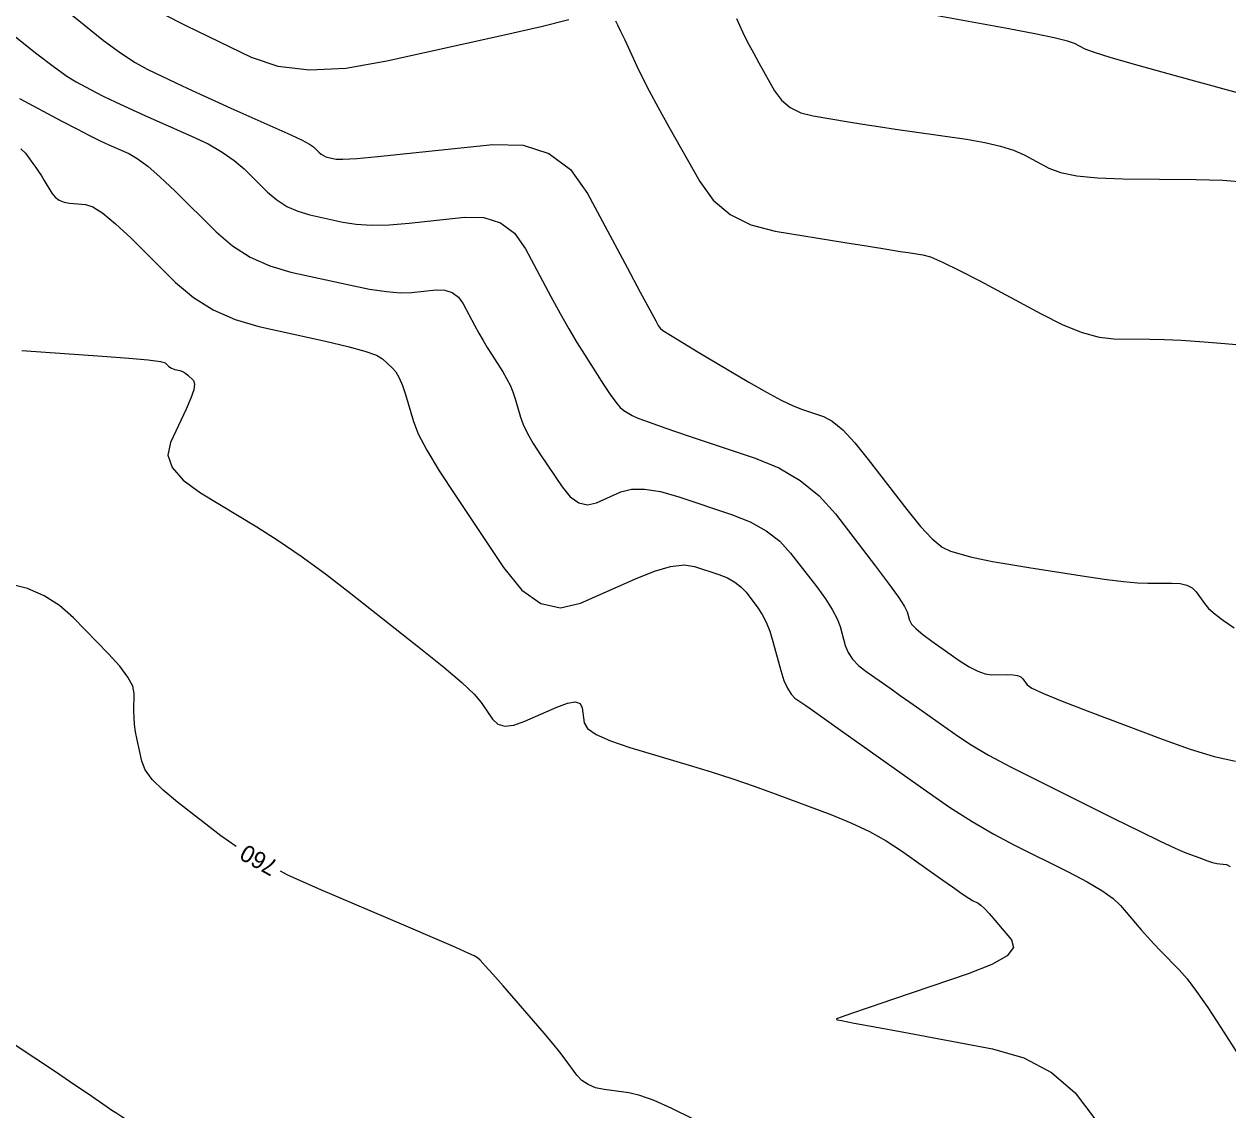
# Model space of a CAD drawing. Extents: x 2082232 to 2083549, y 592624 to 593832.
# Drawn here: x 2082625.36 to 2082675.09, y 592671.24 to 592716.1 of the extents above; entities that cross this region are included whole.
import ezdxf

# ---------------------------------------------------------------- set-up
doc = ezdxf.new("R2010")
doc.units = 0
doc.layers.add('DT_X_Contour_Major', color=7, linetype='Continuous')
doc.layers.add('DT_X_Contour_Minor', color=7, linetype='Continuous')

msp = doc.modelspace()

# ---------------------------------------------------------------- linework, layer by layer
at = {"layer": 'DT_X_Contour_Major'}
for points in [[(2082625.558, 592717.923), (2082627.838, 592716.065), (2082628.641, 592715.429), (2082629.342, 592714.914), (2082629.94, 592714.519), (2082630.435, 592714.245), (2082631.619, 592713.677), (2082632.095, 592713.451), (2082632.634, 592713.202), (2082633.235, 592712.929), (2082633.899, 592712.632), (2082635.755, 592711.808), (2082636.374, 592711.527), (2082636.84, 592711.303), (2082637.153, 592711.136), (2082637.313, 592711.025), (2082637.535, 592710.806), (2082637.622, 592710.731), (2082637.718, 592710.67), (2082637.823, 592710.622), (2082637.936, 592710.59), (2082638.25, 592710.52), (2082638.52, 592710.515), (2082639.095, 592710.552), (2082639.974, 592710.63), (2082641.159, 592710.75), (2082644.725, 592711.126), (2082645.971, 592711.106), (2082647.038, 592710.762), (2082647.924, 592710.096), (2082648.629, 592709.108), (2082650.27, 592706.041), (2082650.812, 592705.029), (2082651.207, 592704.294), (2082651.455, 592703.836), (2082651.556, 592703.655), (2082651.629, 592703.541), (2082651.749, 592703.446), (2082652.057, 592703.247), (2082652.552, 592702.944), (2082653.234, 592702.537), (2082655.302, 592701.314), (2082656.022, 592700.899), (2082656.63, 592700.571), (2082657.125, 592700.331), (2082657.509, 592700.178), (2082658.383, 592699.886), (2082658.744, 592699.694), (2082659.173, 592699.334), (2082659.669, 592698.807), (2082660.231, 592698.114), (2082661.822, 592696.041), (2082662.382, 592695.351), (2082662.871, 592694.834), (2082663.288, 592694.49), (2082663.633, 592694.32), (2082664.456, 592694.098), (2082664.838, 592694.008), (2082665.367, 592693.903), (2082666.042, 592693.784), (2082666.864, 592693.651), (2082669.251, 592693.276), (2082670.08, 592693.153), (2082670.779, 592693.066), (2082671.347, 592693.015), (2082671.783, 592693), (2082672.773, 592693.009), (2082673.113, 592692.989), (2082673.394, 592692.922), (2082673.613, 592692.809), (2082673.773, 592692.649), (2082674.116, 592692.162), (2082674.29, 592691.962), (2082674.554, 592691.728), (2082674.907, 592691.46), (2082675.349, 592691.159)], [(2082634.11, 592682.122), (2082633.477, 592682.564), (2082631.692, 592683.95), (2082631.098, 592684.446), (2082630.653, 592684.895), (2082630.358, 592685.297), (2082630.213, 592685.651), (2082630.026, 592686.532), (2082629.965, 592686.855), (2082629.923, 592687.162), (2082629.9, 592687.453), (2082629.895, 592687.728), (2082629.908, 592688.442), (2082629.845, 592688.745), (2082629.645, 592689.121), (2082629.309, 592689.57), (2082628.837, 592690.09), (2082627.397, 592691.575), (2082626.825, 592692.08), (2082626.189, 592692.482), (2082625.49, 592692.782), (2082624.726, 592692.978)], [(2082652.986, 592670.874), (2082652.115, 592671.303), (2082651.384, 592671.625), (2082650.793, 592671.839), (2082650.341, 592671.945), (2082649.323, 592672.083), (2082648.966, 592672.159), (2082648.659, 592672.285), (2082648.402, 592672.458), (2082648.196, 592672.681), (2082647.711, 592673.34), (2082647.493, 592673.624), (2082647.203, 592673.982), (2082646.84, 592674.414), (2082646.404, 592674.919), (2082645.145, 592676.367), (2082644.725, 592676.846), (2082644.41, 592677.198), (2082644.199, 592677.422), (2082644.093, 592677.519), (2082643.948, 592677.608), (2082643.732, 592677.709), (2082643.19, 592677.947), (2082642.324, 592678.32), (2082641.133, 592678.83), (2082637.523, 592680.37), (2082636.255, 592680.94), (2082635.942, 592681.099)], [(2082624.95, 592673.957), (2082626.648, 592672.822), (2082627.229, 592672.433), (2082627.697, 592672.119), (2082628.052, 592671.878), (2082628.294, 592671.712), (2082628.79, 592671.366), (2082628.981, 592671.236), (2082629.182, 592671.102), (2082629.392, 592670.966), (2082629.612, 592670.827), (2082630.211, 592670.453), (2082630.552, 592670.302), (2082631.128, 592670.128), (2082631.937, 592669.932), (2082632.98, 592669.713), (2082635.484, 592669.217)]]:
    msp.add_lwpolyline(points, dxfattribs=at)
at = {"layer": 'DT_X_Contour_Minor'}
for points in [[(2082631.063, 592716.546), (2082632.063, 592716.024), (2082634.742, 592714.738), (2082635.845, 592714.366), (2082637.146, 592714.216), (2082638.646, 592714.286), (2082640.343, 592714.577), (2082645.132, 592715.647), (2082646.712, 592716.009), (2082647.861, 592716.291)], [(2082677.347, 592712.759), (2082672.868, 592713.982), (2082671.378, 592714.394), (2082670.267, 592714.713), (2082669.536, 592714.938), (2082669.185, 592715.07), (2082668.754, 592715.296), (2082668.463, 592715.397), (2082667.914, 592715.532), (2082667.106, 592715.701), (2082666.04, 592715.903), (2082662.852, 592716.487)], [(2082649.784, 592716.236), (2082649.873, 592716.069), (2082650, 592715.806), (2082650.168, 592715.449), (2082650.665, 592714.37), (2082650.889, 592713.91), (2082651.184, 592713.338), (2082651.553, 592712.656), (2082651.995, 592711.862), (2082653.269, 592709.596), (2082653.822, 592708.831), (2082654.526, 592708.234), (2082655.38, 592707.806), (2082656.384, 592707.546), (2082659.264, 592707.078), (2082660.237, 592706.92), (2082660.997, 592706.798), (2082661.543, 592706.711), (2082661.876, 592706.661), (2082662.481, 592706.573), (2082662.798, 592706.481), (2082663.295, 592706.269), (2082663.974, 592705.939), (2082664.833, 592705.489), (2082667.366, 592704.13), (2082668.267, 592703.683), (2082669.07, 592703.363), (2082669.774, 592703.169), (2082670.38, 592703.101), (2082671.864, 592703.087), (2082672.465, 592703.073), (2082673.153, 592703.041), (2082673.929, 592702.99), (2082674.793, 592702.921), (2082677.212, 592702.712)], [(2082654.784, 592716.331), (2082655.037, 592715.781), (2082655.151, 592715.546), (2082655.302, 592715.255), (2082655.489, 592714.908), (2082655.714, 592714.503), (2082656.363, 592713.349), (2082656.645, 592712.959), (2082657.004, 592712.655), (2082657.439, 592712.437), (2082657.95, 592712.305), (2082659.417, 592712.066), (2082659.999, 592711.973), (2082660.646, 592711.873), (2082661.358, 592711.767), (2082662.133, 592711.653), (2082664.288, 592711.341), (2082665.043, 592711.213), (2082665.692, 592711.063), (2082666.235, 592710.891), (2082666.672, 592710.696), (2082667.695, 592710.147), (2082668.173, 592709.966), (2082668.84, 592709.833), (2082669.696, 592709.75), (2082670.74, 592709.715), (2082673.779, 592709.687), (2082674.873, 592709.652), (2082675.878, 592709.565)], [(2082624.919, 592715.646), (2082625.824, 592714.921), (2082626.556, 592714.358), (2082627.115, 592713.956), (2082627.502, 592713.716), (2082628.302, 592713.292), (2082628.654, 592713.113), (2082629.113, 592712.893), (2082629.678, 592712.632), (2082630.348, 592712.331), (2082632.277, 592711.475), (2082632.955, 592711.149), (2082633.543, 592710.814), (2082634.04, 592710.47), (2082634.446, 592710.117), (2082635.41, 592709.164), (2082635.79, 592708.837), (2082636.208, 592708.571), (2082636.663, 592708.367), (2082637.155, 592708.224), (2082638.518, 592707.923), (2082639.073, 592707.836), (2082639.714, 592707.8), (2082640.443, 592707.814), (2082641.26, 592707.879), (2082643.553, 592708.121), (2082644.354, 592708.108), (2082645.04, 592707.887), (2082645.61, 592707.459), (2082646.064, 592706.823), (2082647.119, 592704.851), (2082647.502, 592704.146), (2082647.86, 592703.51), (2082648.193, 592702.943), (2082648.502, 592702.445), (2082649.291, 592701.209), (2082649.565, 592700.794), (2082649.797, 592700.476), (2082649.987, 592700.255), (2082650.134, 592700.132), (2082650.47, 592699.933), (2082650.71, 592699.825), (2082651.177, 592699.649), (2082651.872, 592699.405), (2082652.794, 592699.094), (2082655.557, 592698.173), (2082656.541, 592697.769), (2082657.421, 592697.25), (2082658.197, 592696.615), (2082658.87, 592695.865), (2082660.525, 592693.708), (2082661.072, 592692.984), (2082661.474, 592692.429), (2082661.729, 592692.042), (2082661.839, 592691.825), (2082661.936, 592691.469), (2082662.021, 592691.315), (2082662.203, 592691.121), (2082662.482, 592690.885), (2082662.858, 592690.608), (2082663.991, 592689.814), (2082664.394, 592689.554), (2082664.752, 592689.368), (2082665.065, 592689.258), (2082665.335, 592689.223), (2082665.994, 592689.228), (2082666.218, 592689.219), (2082666.396, 592689.186), (2082666.529, 592689.129), (2082666.617, 592689.05), (2082666.788, 592688.806), (2082666.992, 592688.67), (2082667.474, 592688.446), (2082668.234, 592688.134), (2082669.273, 592687.732), (2082672.415, 592686.544), (2082673.531, 592686.148), (2082674.526, 592685.848), (2082675.399, 592685.647)], [(2082625.162, 592713.021), (2082626.915, 592712.091), (2082627.529, 592711.769), (2082628.057, 592711.5), (2082628.497, 592711.283), (2082628.851, 592711.119), (2082629.679, 592710.751), (2082630.031, 592710.551), (2082630.465, 592710.227), (2082630.981, 592709.78), (2082631.58, 592709.209), (2082633.286, 592707.522), (2082633.959, 592706.943), (2082634.698, 592706.473), (2082635.503, 592706.111), (2082636.374, 592705.858), (2082638.786, 592705.326), (2082639.625, 592705.157), (2082640.334, 592705.048), (2082640.912, 592704.998), (2082641.36, 592705.009), (2082642.38, 592705.116), (2082642.737, 592705.11), (2082643.042, 592705.012), (2082643.296, 592704.821), (2082643.498, 592704.539), (2082643.967, 592703.661), (2082644.143, 592703.339), (2082644.318, 592703.032), (2082644.492, 592702.738), (2082644.666, 592702.459), (2082645.129, 592701.734), (2082645.291, 592701.461), (2082645.431, 592701.185), (2082645.547, 592700.906), (2082645.641, 592700.623), (2082645.862, 592699.867), (2082645.976, 592699.557), (2082646.153, 592699.193), (2082646.392, 592698.776), (2082646.694, 592698.306), (2082647.582, 592696.98), (2082647.921, 592696.566), (2082648.27, 592696.319), (2082648.632, 592696.238), (2082649.004, 592696.324), (2082650.013, 592696.775), (2082650.446, 592696.889), (2082650.988, 592696.892), (2082651.641, 592696.785), (2082652.404, 592696.568), (2082654.584, 592695.841), (2082655.349, 592695.537), (2082656.011, 592695.17), (2082656.57, 592694.739), (2082657.024, 592694.246), (2082658.099, 592692.846), (2082658.461, 592692.35), (2082658.743, 592691.912), (2082658.944, 592691.533), (2082659.064, 592691.212), (2082659.277, 592690.433), (2082659.393, 592690.145), (2082659.583, 592689.865), (2082659.845, 592689.593), (2082660.18, 592689.329), (2082661.17, 592688.635), (2082661.55, 592688.368), (2082661.946, 592688.089), (2082662.358, 592687.797), (2082662.787, 592687.493), (2082663.953, 592686.665), (2082664.484, 592686.319), (2082665.203, 592685.903), (2082666.11, 592685.417), (2082667.204, 592684.861), (2082670.373, 592683.283), (2082671.447, 592682.753), (2082672.29, 592682.345), (2082672.904, 592682.06), (2082673.287, 592681.897), (2082674.003, 592681.627), (2082674.25, 592681.537), (2082674.457, 592681.47), (2082674.623, 592681.427), (2082674.748, 592681.407), (2082675.026, 592681.385), (2082675.187, 592681.301)], [(2082625.225, 592710.944), (2082625.41, 592710.763), (2082625.721, 592710.343), (2082625.838, 592710.181), (2082625.956, 592710.01), (2082626.073, 592709.83), (2082626.191, 592709.64), (2082626.506, 592709.123), (2082626.64, 592708.951), (2082626.807, 592708.824), (2082627.006, 592708.74), (2082627.237, 592708.701), (2082627.897, 592708.654), (2082628.199, 592708.554), (2082628.613, 592708.287), (2082629.138, 592707.853), (2082629.773, 592707.253), (2082631.615, 592705.431), (2082632.349, 592704.804), (2082633.167, 592704.292), (2082634.07, 592703.894), (2082635.059, 592703.61), (2082637.807, 592703.004), (2082638.728, 592702.788), (2082639.428, 592702.594), (2082639.909, 592702.422), (2082640.168, 592702.273), (2082640.568, 592701.903), (2082640.714, 592701.73), (2082640.853, 592701.487), (2082640.986, 592701.174), (2082641.111, 592700.792), (2082641.436, 592699.68), (2082641.635, 592699.176), (2082641.991, 592698.498), (2082642.503, 592697.645), (2082643.171, 592696.619), (2082645.161, 592693.648), (2082645.92, 592692.721), (2082646.704, 592692.166), (2082647.513, 592691.985), (2082648.348, 592692.178), (2082650.608, 592693.188), (2082651.396, 592693.504), (2082652.066, 592693.693), (2082652.619, 592693.757), (2082653.054, 592693.695), (2082654.056, 592693.361), (2082654.409, 592693.221), (2082654.713, 592693.052), (2082654.97, 592692.854), (2082655.179, 592692.627), (2082655.673, 592691.983), (2082655.851, 592691.715), (2082656.013, 592691.396), (2082656.159, 592691.023), (2082656.29, 592690.599), (2082656.619, 592689.397), (2082656.748, 592688.988), (2082656.888, 592688.662), (2082657.04, 592688.419), (2082657.203, 592688.259), (2082657.654, 592687.943), (2082657.925, 592687.751), (2082658.403, 592687.413), (2082659.085, 592686.929), (2082659.973, 592686.298), (2082662.615, 592684.421), (2082663.587, 592683.753), (2082664.52, 592683.156), (2082665.416, 592682.632), (2082666.273, 592682.178), (2082668.509, 592681.066), (2082669.271, 592680.667), (2082669.882, 592680.303), (2082670.342, 592679.976), (2082670.65, 592679.684), (2082671.268, 592678.954), (2082671.507, 592678.678), (2082671.761, 592678.395), (2082672.028, 592678.108), (2082672.309, 592677.814), (2082673.077, 592677.025), (2082673.4, 592676.654), (2082673.794, 592676.135), (2082674.259, 592675.467), (2082674.793, 592674.651), (2082676.314, 592672.276)], [(2082625.267, 592702.622), (2082628.591, 592702.388), (2082629.688, 592702.305), (2082630.486, 592702.231), (2082630.986, 592702.166), (2082631.187, 592702.111), (2082631.325, 592701.974), (2082631.38, 592701.927), (2082631.442, 592701.888), (2082631.51, 592701.858), (2082631.584, 592701.837), (2082631.79, 592701.792), (2082631.869, 592701.767), (2082631.95, 592701.725), (2082632.034, 592701.668), (2082632.121, 592701.595), (2082632.356, 592701.377), (2082632.402, 592701.242), (2082632.367, 592700.998), (2082632.248, 592700.646), (2082632.047, 592700.186), (2082631.4, 592698.814), (2082631.296, 592698.299), (2082631.47, 592697.78), (2082631.921, 592697.259), (2082632.65, 592696.735), (2082634.964, 592695.335), (2082635.858, 592694.769), (2082636.804, 592694.121), (2082637.804, 592693.392), (2082638.855, 592692.58), (2082641.73, 592690.308), (2082642.696, 592689.53), (2082643.436, 592688.899), (2082643.95, 592688.416), (2082644.238, 592688.079), (2082644.707, 592687.379), (2082644.923, 592687.177), (2082645.218, 592687.096), (2082645.593, 592687.136), (2082646.047, 592687.296), (2082647.365, 592687.885), (2082647.801, 592688.049), (2082648.121, 592688.1), (2082648.325, 592688.036), (2082648.413, 592687.858), (2082648.491, 592687.233), (2082648.632, 592686.994), (2082648.994, 592686.745), (2082649.578, 592686.487), (2082650.384, 592686.219), (2082652.83, 592685.491), (2082653.74, 592685.212), (2082654.636, 592684.92), (2082655.519, 592684.616), (2082656.387, 592684.3), (2082658.685, 592683.44), (2082659.513, 592683.105), (2082660.274, 592682.745), (2082660.968, 592682.36), (2082661.596, 592681.951), (2082663.179, 592680.826), (2082663.709, 592680.452), (2082664.112, 592680.172), (2082664.388, 592679.987), (2082664.538, 592679.897), (2082664.766, 592679.783), (2082664.874, 592679.707), (2082665.025, 592679.566), (2082665.219, 592679.358), (2082665.457, 592679.085), (2082666.15, 592678.267), (2082666.233, 592677.95), (2082665.963, 592677.61), (2082665.338, 592677.249), (2082664.359, 592676.865), (2082661.279, 592675.813), (2082660.267, 592675.468), (2082659.542, 592675.22), (2082659.104, 592675.069), (2082658.953, 592675.016), (2082658.932, 592675.005), (2082658.925, 592675.001), (2082658.92, 592674.998), (2082658.917, 592674.995), (2082658.916, 592674.994), (2082658.916, 592674.99), (2082658.916, 592674.989), (2082658.916, 592674.988), (2082658.917, 592674.987), (2082658.918, 592674.986), (2082658.922, 592674.984), (2082658.924, 592674.983), (2082658.926, 592674.981), (2082658.93, 592674.979), (2082658.934, 592674.975), (2082658.947, 592674.965), (2082659.123, 592674.93), (2082659.641, 592674.832), (2082660.502, 592674.671), (2082661.704, 592674.447), (2082665.368, 592673.767), (2082666.663, 592673.394), (2082667.797, 592672.787), (2082668.772, 592671.946), (2082669.587, 592670.87)]]:
    msp.add_lwpolyline(points, dxfattribs=at)

# ---------------------------------------------------------------- texts
at = {"layer": 'DT_X_Contour_Major'}
msp.add_text('760', height=0.7, rotation=150.8012, dxfattribs=at).set_placement((2082635.903, 592681.484))

doc.saveas('drawing.dxf')
